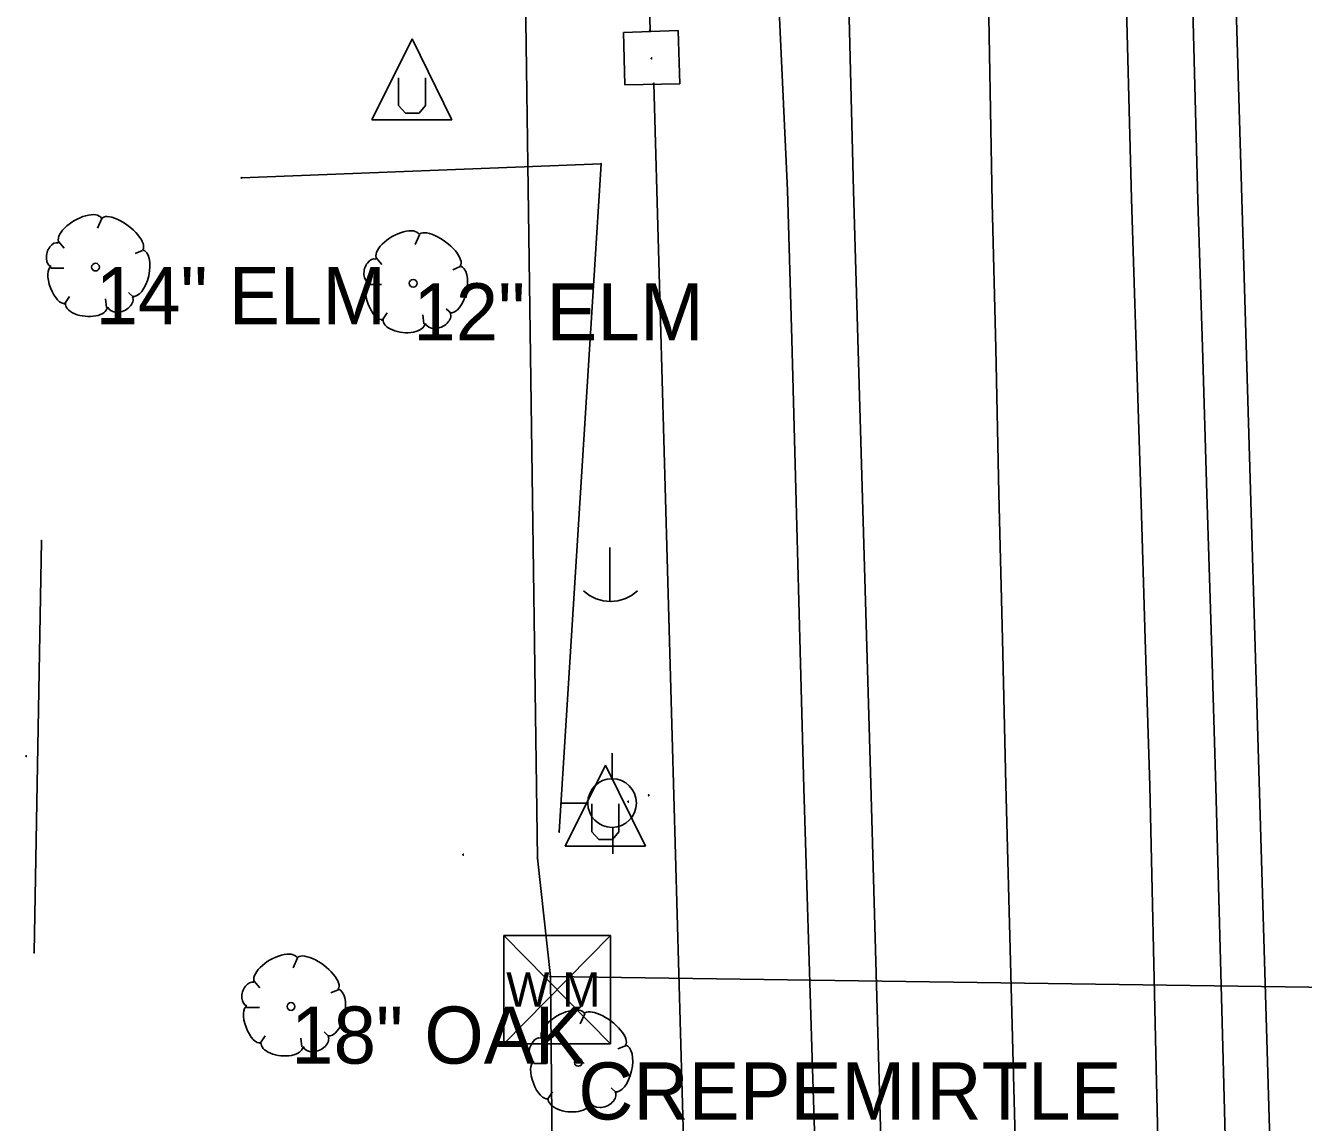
# Model space of a CAD drawing. Extents: x 1930288 to 1941089, y 588389 to 611475.
# Drawn here: x 1930811.5 to 1930923.3, y 597231.2 to 597327.2 of the extents above; entities that cross this region are included whole.
import ezdxf

# ---------------------------------------------------------------- set-up
doc = ezdxf.new("R2010")
doc.units = 0
for name, color, linetype in [('S_BASELINE', 7, 'Continuous'), ('S_BUILDING', 7, 'Continuous'), ('S_DRG_PT_SYM', 7, 'Continuous'), ('S_DROP_INLET', 7, 'Continuous'), ('S_EDGE_PAVEMENT', 7, 'Continuous'), ('S_MSC_PT_SYM', 7, 'Continuous'), ('S_PAVEMENT_CROWN', 7, 'Continuous'), ('S_SHOULDER', 7, 'Continuous'), ('S_STORM_SEWER', 7, 'Continuous'), ('S_STR_PT_SYM', 7, 'Continuous'), ('S_TREE', 7, 'Continuous'), ('S_TREE_ANNOT', 7, 'Continuous'), ('S_UNDERGROUND_CABLE', 7, 'Continuous'), ('S_UTILITY_POLE', 7, 'Continuous'), ('S_UTL_PT_SYM', 7, 'Continuous'), ('S_WATER_UTILITIES', 7, 'Continuous')]:
    doc.layers.add(name, color=color, linetype=linetype)

msp = doc.modelspace()

# ---------------------------------------------------------------- linework, layer by layer
at = {"layer": 'S_BASELINE'}
msp.add_line((1930922.05, 597172.86), (1930894.27, 598110.49), dxfattribs=at)
at = {"layer": 'S_BUILDING'}
msp.add_line((1930812.23, 597246.1), (1930812.88, 597282.12), dxfattribs=at)
at = {"layer": 'S_DRG_PT_SYM'}
msp.add_lwpolyline([(1930866.27, 597324.37), (1930866.27, 597324.42), (1930866.27, 597324.37), (1930866.22, 597324.37), (1930866.27, 597324.37), (1930866.27, 597324.32), (1930866.27, 597324.37), (1930866.32, 597324.37)], dxfattribs=at)
at = {"layer": 'S_DROP_INLET'}
for points in [[(1930863.82, 597326.64), (1930868.59, 597326.79), (1930868.73, 597322.14), (1930863.92, 597322.04)], [(1930863.92, 597322.04), (1930863.82, 597326.64)]]:
    msp.add_lwpolyline(points, dxfattribs=at)
at = {"layer": 'S_EDGE_PAVEMENT'}
for points in [[(1930883.41, 597333.75), (1930883.95, 597312.79), (1930884.33, 597299.81), (1930884.71, 597286.83), (1930885.08, 597273.84), (1930885.46, 597260.86), (1930886.13, 597237.01), (1930886.8, 597213.16), (1930887.21, 597200.45), (1930887.63, 597187.75), (1930888.05, 597175.05), (1930888.46, 597162.35), (1930888.4, 597148.75), (1930888.66, 597144.03), (1930888.95, 597131.01), (1930889.24, 597118)], [(1930907.71, 597333.22), (1930908.28, 597312.07), (1930908.68, 597299.22), (1930909.07, 597286.37), (1930909.47, 597273.53), (1930909.86, 597260.68), (1930910.44, 597235.98), (1930911.01, 597211.28), (1930911.31, 597198.77), (1930911.61, 597186.25), (1930911.91, 597173.74), (1930912.21, 597161.22), (1930912.7, 597150.37), (1930912.58, 597146.46), (1930912.96, 597132.04), (1930913.35, 597117.63)]]:
    msp.add_lwpolyline(points, dxfattribs=at)
at = {"layer": 'S_MSC_PT_SYM'}
for points in [[(1930866.13, 597326.83), (1930866.13, 597326.88), (1930866.13, 597326.83), (1930866.08, 597326.83), (1930866.13, 597326.83), (1930866.13, 597326.78), (1930866.13, 597326.83), (1930866.18, 597326.83)], [(1930866.47, 597322.17), (1930866.47, 597322.22), (1930866.47, 597322.17), (1930866.42, 597322.17), (1930866.47, 597322.17), (1930866.47, 597322.12), (1930866.47, 597322.17), (1930866.52, 597322.17)], [(1930861.84, 597315.12), (1930861.84, 597315.17), (1930861.84, 597315.12), (1930861.79, 597315.12), (1930861.84, 597315.12), (1930861.84, 597315.07), (1930861.84, 597315.12), (1930861.89, 597315.12)], [(1930830.38, 597313.9), (1930830.38, 597313.95), (1930830.38, 597313.9), (1930830.33, 597313.9), (1930830.38, 597313.9), (1930830.38, 597313.85), (1930830.38, 597313.9), (1930830.43, 597313.9)], [(1930811.53, 597263.28), (1930811.53, 597263.33), (1930811.53, 597263.28), (1930811.48, 597263.28), (1930811.53, 597263.28), (1930811.53, 597263.23), (1930811.53, 597263.28), (1930811.58, 597263.28)], [(1930864.23, 597259.3), (1930864.23, 597259.35), (1930864.23, 597259.3), (1930864.18, 597259.3), (1930864.23, 597259.3), (1930864.23, 597259.25), (1930864.23, 597259.3), (1930864.28, 597259.3)], [(1930866.02, 597259.85), (1930866.02, 597259.9), (1930866.02, 597259.85), (1930865.97, 597259.85), (1930866.02, 597259.85), (1930866.02, 597259.8), (1930866.02, 597259.85), (1930866.07, 597259.85)], [(1930858.18, 597256.66), (1930858.18, 597256.71), (1930858.18, 597256.66), (1930858.13, 597256.66), (1930858.18, 597256.66), (1930858.18, 597256.61), (1930858.18, 597256.66), (1930858.23, 597256.66)], [(1930849.78, 597254.65), (1930849.78, 597254.7), (1930849.78, 597254.65), (1930849.73, 597254.65), (1930849.78, 597254.65), (1930849.78, 597254.6), (1930849.78, 597254.65), (1930849.83, 597254.65)]]:
    msp.add_lwpolyline(points, dxfattribs=at)
at = {"layer": 'S_PAVEMENT_CROWN'}
msp.add_lwpolyline([(1930895.7, 597332.87), (1930896.08, 597311.73), (1930896.38, 597299), (1930896.67, 597286.26), (1930896.97, 597273.52), (1930897.26, 597260.78), (1930897.91, 597236.44), (1930898.56, 597212.1), (1930898.93, 597199.57), (1930899.29, 597187.04), (1930899.66, 597174.51), (1930900.03, 597161.98), (1930900.3, 597149.26), (1930900.31, 597149.02), (1930900.31, 597146.15), (1930900.73, 597131.95), (1930901.14, 597117.75)], dxfattribs=at)
at = {"layer": 'S_SHOULDER'}
for points in [[(1930877.23, 597332.98), (1930878.17, 597312.83), (1930878.53, 597299.75), (1930878.88, 597286.66), (1930879.23, 597273.57), (1930879.58, 597260.49), (1930880.33, 597236.83), (1930881.08, 597213.18), (1930881.06, 597198.79), (1930881.29, 597182.76), (1930881.53, 597166.72), (1930882.41, 597146.46), (1930882.75, 597138.66), (1930883.36, 597134.37), (1930883.43, 597130.36), (1930883.65, 597117.6)], [(1930913.51, 597333.17), (1930914.07, 597311.92), (1930914.47, 597299.07), (1930914.87, 597286.23), (1930915.26, 597273.39), (1930915.66, 597260.55), (1930916.31, 597235.65), (1930916.95, 597210.75), (1930917.33, 597185.99), (1930917.7, 597161.23), (1930918.23, 597149.46), (1930918.38, 597145.09), (1930918.82, 597130.98), (1930919.27, 597116.87)]]:
    msp.add_lwpolyline(points, dxfattribs=at)
at = {"layer": 'S_STORM_SEWER'}
for p, q in [((1930862.1, 597464.02), (1930866.13, 597326.83)), ((1930866.47, 597322.17), (1930871.19, 597153.07))]:
    msp.add_line(p, q, dxfattribs=at)
at = {"layer": 'S_STR_PT_SYM'}
for points in [[(1930812.88, 597282.12), (1930812.88, 597282.17), (1930812.88, 597282.12), (1930812.83, 597282.12), (1930812.88, 597282.12), (1930812.88, 597282.07), (1930812.88, 597282.12), (1930812.93, 597282.12)], [(1930812.23, 597246.1), (1930812.23, 597246.15), (1930812.23, 597246.1), (1930812.18, 597246.1), (1930812.23, 597246.1), (1930812.23, 597246.05), (1930812.23, 597246.1), (1930812.28, 597246.1)]]:
    msp.add_lwpolyline(points, dxfattribs=at)
at = {"layer": 'S_TREE'}
for p, q in [((1930830.38, 597313.9), (1930861.84, 597315.12)), ((1930861.84, 597315.12), (1930858.18, 597256.66)), ((1930818.16, 597310.34), (1930817.77, 597309.49)), ((1930814.36, 597308.32), (1930814.86, 597307.74)), ((1930845.95, 597308.92), (1930845.57, 597308.07)), ((1930821.72, 597307.55), (1930821.06, 597307.28)), ((1930813.7, 597306), (1930814.83, 597306)), ((1930842.16, 597306.9), (1930842.66, 597306.32)), ((1930849.52, 597306.13), (1930848.86, 597305.86)), ((1930820.95, 597303.44), (1930820.48, 597303.87)), ((1930841.5, 597304.58), (1930842.62, 597304.58)), ((1930814.86, 597302.82), (1930815.33, 597303.52)), ((1930818.55, 597302.55), (1930818.47, 597303.32)), ((1930842.66, 597301.4), (1930843.12, 597302.1)), ((1930846.34, 597301.13), (1930846.26, 597301.91)), ((1930848.74, 597302.02), (1930848.28, 597302.45)), ((1930835.27, 597245.61), (1930834.89, 597244.76)), ((1930831.48, 597243.59), (1930831.98, 597243.01)), ((1930838.84, 597242.82), (1930838.18, 597242.55)), ((1930830.82, 597241.27), (1930831.94, 597241.27)), ((1930860.41, 597240.71), (1930860.02, 597239.86)), ((1930831.98, 597238.09), (1930832.44, 597238.79)), ((1930838.06, 597238.71), (1930837.6, 597239.14)), ((1930835.66, 597237.82), (1930835.58, 597238.59)), ((1930856.61, 597238.7), (1930857.12, 597238.12)), ((1930863.97, 597237.92), (1930863.32, 597237.65)), ((1930855.95, 597236.37), (1930857.08, 597236.37)), ((1930857.12, 597233.2), (1930857.58, 597233.89)), ((1930860.8, 597232.92), (1930860.72, 597233.7)), ((1930863.2, 597233.82), (1930862.73, 597234.24))]:
    msp.add_line(p, q, dxfattribs=at)
for centre in [(1930817.6, 597306.09), (1930845.4, 597304.67), (1930834.71, 597241.36), (1930859.85, 597236.47)]:
    msp.add_circle(centre, 0.341, dxfattribs=at)
for centre, major_axis, ratio, start_param, end_param in [((1930816.26, 597309.29), (1.86, 1.08), 0.471018, 0, 3.141593), ((1930819.92, 597308.97), (-1.81, 1.36), 0.405113, 3.141593, 6.283186), ((1930844.06, 597307.88), (1.86, 1.08), 0.471018, 0, 3.141593), ((1930847.71, 597307.55), (-1.81, 1.36), 0.405113, 3.141593, 6.283186), ((1930814.03, 597307.18), (0.31, 1.03), 0.646762, 0, 3.141593), ((1930821.27, 597305.56), (0.46, 2.04), 0.482994, 3.141593, 6.283185), ((1930814.33, 597304.53), (-0.61, 1.6), 0.420543, 6.283185, 9.424777), ((1930841.82, 597305.76), (0.31, 1.03), 0.646762, 0, 3.141593), ((1930849.07, 597304.14), (0.46, 2.04), 0.482994, 3.141593, 6.283185), ((1930842.13, 597303.11), (-0.61, 1.6), 0.420543, 6.283185, 9.424777), ((1930816.79, 597302.75), (-1.83, 0.19), 0.529943, 0, 3.141593), ((1930819.75, 597303.04), (1.09, 0.46), 0.711534, 3.141592, 6.283185), ((1930844.59, 597301.33), (-1.83, 0.19), 0.529943, 0, 3.141593), ((1930847.55, 597301.62), (1.09, 0.46), 0.711534, 3.141592, 6.283185), ((1930833.38, 597244.56), (1.86, 1.08), 0.471018, 0, 3.141593), ((1930837.03, 597244.24), (-1.81, 1.36), 0.405113, 3.141593, 6.283186), ((1930831.14, 597242.45), (0.31, 1.03), 0.646762, 0, 3.141593), ((1930838.39, 597240.83), (0.46, 2.04), 0.482994, 3.141593, 6.283185), ((1930831.45, 597239.8), (-0.61, 1.6), 0.420543, 6.283185, 9.424777), ((1930858.52, 597239.67), (1.86, 1.08), 0.471018, 0, 3.141593), ((1930862.17, 597239.35), (-1.81, 1.36), 0.405113, 3.141593, 6.283186), ((1930836.87, 597238.31), (1.09, 0.46), 0.711534, 3.141592, 6.283185), ((1930833.91, 597238.02), (-1.83, 0.19), 0.529943, 0, 3.141593), ((1930856.28, 597237.56), (0.31, 1.03), 0.646762, 0, 3.141593), ((1930863.53, 597235.94), (0.46, 2.04), 0.482994, 3.141593, 6.283185), ((1930856.59, 597234.91), (-0.61, 1.6), 0.420543, 6.283185, 9.424777), ((1930859.05, 597233.12), (-1.83, 0.19), 0.529943, 0, 3.141593), ((1930862, 597233.42), (1.09, 0.46), 0.711534, 3.141592, 6.283185)]:
    msp.add_ellipse(centre, major_axis=major_axis, ratio=ratio, start_param=start_param, end_param=end_param, dxfattribs=at)
at = {"layer": 'S_UNDERGROUND_CABLE'}
for p, q in [((1930845.31, 597326.08), (1930841.78, 597318.99)), ((1930845.31, 597326.08), (1930848.79, 597318.99)), ((1930844.11, 597320.23), (1930844.11, 597322.67)), ((1930846.47, 597322.67), (1930846.47, 597320.23)), ((1930844.73, 597319.57), (1930844.11, 597320.23)), ((1930845.93, 597319.57), (1930844.73, 597319.57)), ((1930846.47, 597320.23), (1930845.93, 597319.57)), ((1930841.78, 597318.99), (1930848.79, 597318.99)), ((1930862.23, 597262.5), (1930858.7, 597255.41)), ((1930862.23, 597262.5), (1930865.72, 597255.41)), ((1930861.03, 597256.65), (1930861.03, 597259.09)), ((1930863.39, 597259.09), (1930863.39, 597256.65)), ((1930861.65, 597255.99), (1930861.03, 597256.65)), ((1930863.39, 597256.65), (1930862.85, 597255.99)), ((1930862.85, 597255.99), (1930861.65, 597255.99)), ((1930858.7, 597255.41), (1930865.72, 597255.41))]:
    msp.add_line(p, q, dxfattribs=at)
at = {"layer": 'S_UTILITY_POLE'}
for p, q in [((1930862.61, 597281.54), (1930862.61, 597276.81)), ((1930862.81, 597261.28), (1930862.81, 597263.53)), ((1930860.71, 597259.15), (1930858.39, 597259.15)), ((1930862.88, 597254.73), (1930862.88, 597257.06))]:
    msp.add_line(p, q, dxfattribs=at)
msp.add_circle((1930862.81, 597259.17), 2.13, dxfattribs=at)
msp.add_arc((1930862.67, 597280.23), 3.41, 226.3972, 313.6028, dxfattribs=at)
at = {"layer": 'S_UTL_PT_SYM'}
for points in [[(1930866.13, 597326.83), (1930866.13, 597326.88), (1930866.13, 597326.83), (1930866.08, 597326.83), (1930866.13, 597326.83), (1930866.13, 597326.78), (1930866.13, 597326.83), (1930866.18, 597326.83)], [(1930866.27, 597324.37), (1930866.27, 597324.42), (1930866.27, 597324.37), (1930866.22, 597324.37), (1930866.27, 597324.37), (1930866.27, 597324.32), (1930866.27, 597324.37), (1930866.32, 597324.37)], [(1930866.47, 597322.17), (1930866.47, 597322.22), (1930866.47, 597322.17), (1930866.42, 597322.17), (1930866.47, 597322.17), (1930866.47, 597322.12), (1930866.47, 597322.17), (1930866.52, 597322.17)], [(1930856.29, 597254.36), (1930856.29, 597254.41), (1930856.29, 597254.36), (1930856.24, 597254.36), (1930856.29, 597254.36), (1930856.29, 597254.31), (1930856.29, 597254.36), (1930856.34, 597254.36)], [(1930857.41, 597243.98), (1930857.41, 597244.03), (1930857.41, 597243.98), (1930857.36, 597243.98), (1930857.41, 597243.98), (1930857.41, 597243.93), (1930857.41, 597243.98), (1930857.46, 597243.98)], [(1930857.41, 597243.98), (1930857.41, 597244.03), (1930857.41, 597243.98), (1930857.36, 597243.98), (1930857.41, 597243.98), (1930857.41, 597243.93), (1930857.41, 597243.98), (1930857.46, 597243.98)]]:
    msp.add_lwpolyline(points, dxfattribs=at)
at = {"layer": 'S_WATER_UTILITIES'}
for p, q in [((1930854.35, 597391.03), (1930856.29, 597254.36)), ((1930856.29, 597254.36), (1930857.41, 597243.98)), ((1930853.34, 597247.59), (1930862.68, 597247.59)), ((1930853.34, 597247.59), (1930853.34, 597238.09)), ((1930853.34, 597247.59), (1930862.68, 597238.09)), ((1930862.68, 597247.59), (1930853.34, 597238.09)), ((1930862.68, 597247.59), (1930862.68, 597238.09)), ((1930857.41, 597243.98), (1930858.51, 597141.08)), ((1930857.41, 597243.98), (1930971.97, 597242.4)), ((1930853.34, 597238.09), (1930862.68, 597238.09))]:
    msp.add_line(p, q, dxfattribs=at)

# ---------------------------------------------------------------- texts
at = {"layer": 'S_TREE_ANNOT'}
for s, p in [('14" ELM', (1930817.6, 597301.09)), ('12" ELM', (1930845.4, 597299.67)), ('18" OAK', (1930834.71, 597236.36)), ('CREPEMIRTLE', (1930859.85, 597231.47))]:
    msp.add_text(s, height=5, dxfattribs=at).set_placement(p)
at = {"layer": 'S_WATER_UTILITIES'}
msp.add_text('W M', height=3, rotation=360, dxfattribs=at).set_placement((1930853.54, 597241.35))

doc.saveas('drawing.dxf')
